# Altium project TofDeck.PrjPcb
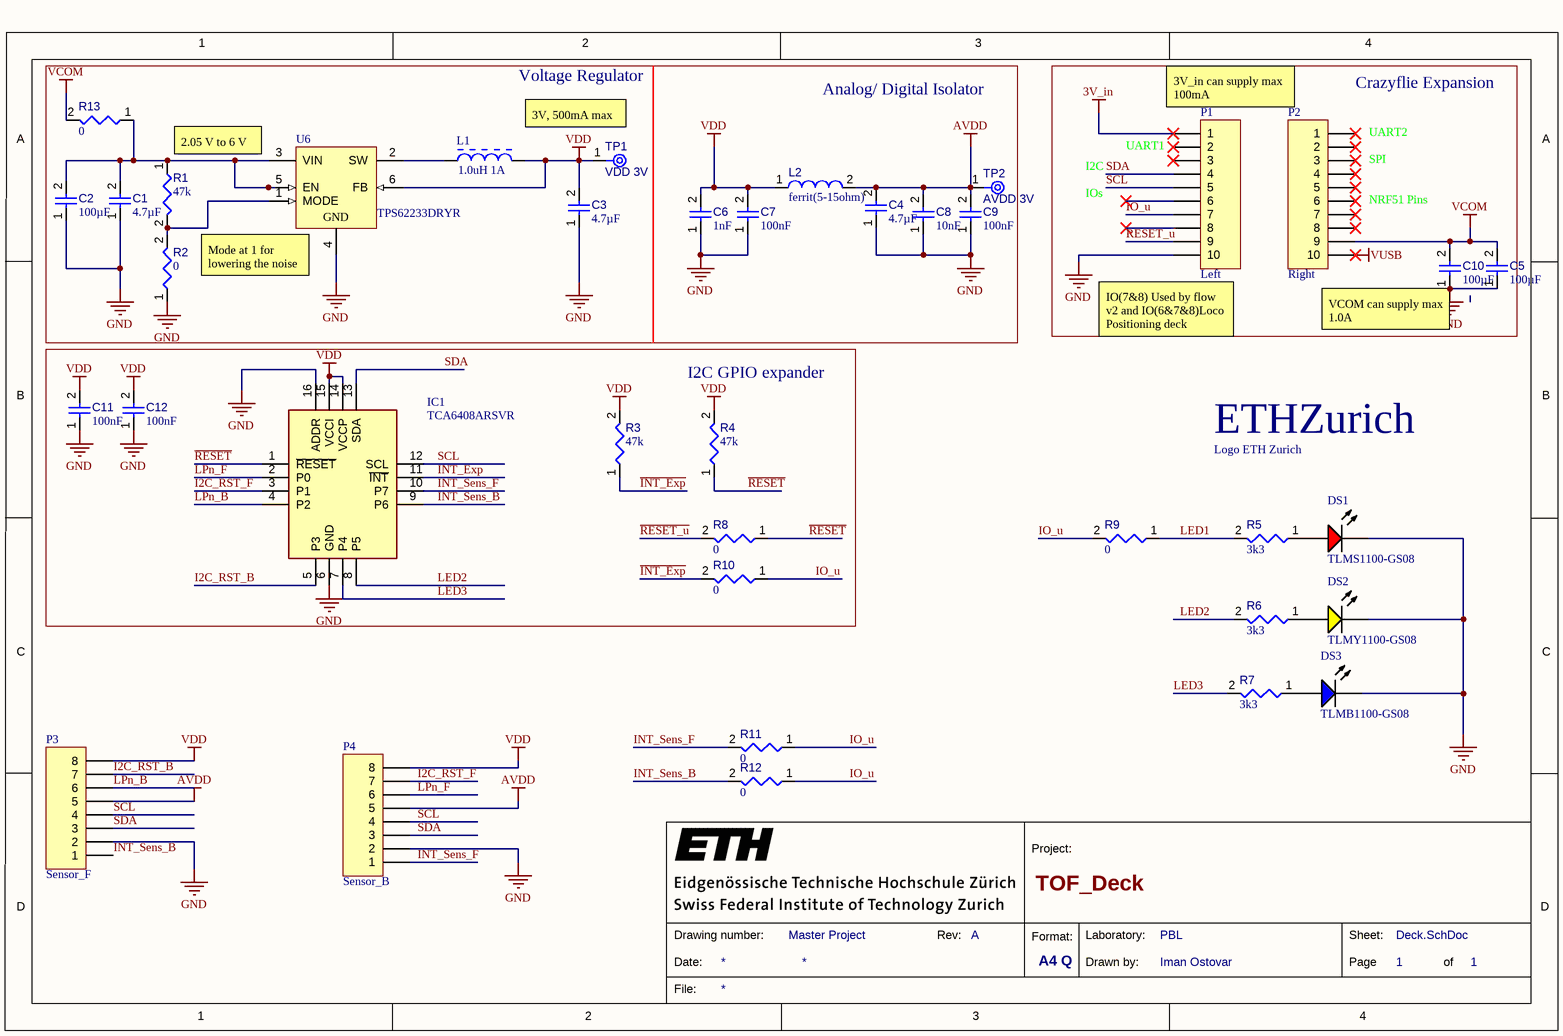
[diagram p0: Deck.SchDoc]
1 sheet, 39 parts. Net scope: global (net labels, ports and power ports of the same name join across sheets).
Board file: Deck.PcbDoc

## Sheet Deck.SchDoc: TOF_Deck
size A4; Author: Iman Ostovar; CompanyName: ETH Zürich; DrawnBy: Iman Ostovar; Engineer: Iman Ostovar; Organization: PBL; DocumentNumber: Master Project; Revision: A; SheetNumber: 1; SheetTotal: 1

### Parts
A1  Logo ETH Zurich  [eth-zurich_3mm]  (no BOM)
C1  value 4.7µF  [CAPC1005X55X25ML5T10]  (hidden comment: Capacitor 1 uF +/- 10% 6.3 V 1005)
C2  value 100µF  [CAPC0805(2012)145_L]  (hidden comment: Capacitor 100µF +/-20% 6.3V 0805)
C3  value 4.7µF  [CAPC1005X55X25ML5T10]  (hidden comment: Capacitor 1 uF +/- 10% 6.3 V 1005)
C4  value 4.7µF  [CAPC1005X55X25ML5T10]  (hidden comment: Capacitor 1 uF +/- 10% 6.3 V 1005)
C5  value 100µF  [CAPC0805(2012)145_L]  (hidden comment: Capacitor 100µF +/-20% 6.3V 0805)
C6  value 1nF  [CAPC0402(1005)60_L]  (hidden comment: Capacitor 100nF +/-20% 25V 0402)
C7  value 100nF  [CAPC0402(1005)60_L]  (hidden comment: Capacitor 100nF +/-20% 25V 0402)
C8  value 10nF  [CAPC0402(1005)60_L]  (hidden comment: Capacitor 100nF +/-20% 25V 0402)
C9  value 100nF  [CAPC0402(1005)60_L]  (hidden comment: Capacitor 100nF +/-20% 25V 0402)
C10  value 100µF  [CAPC0805(2012)145_L]  (hidden comment: Capacitor 100µF +/-20% 6.3V 0805)
C11  value 100nF  [CAPC0402(1005)60_L]  (hidden comment: Capacitor 100nF +/-20% 25V 0402)
C12  value 100nF  [CAPC0402(1005)60_L]  (hidden comment: Capacitor 100nF +/-20% 25V 0402)
DS1  TLMS1100-GS08  [VISH-TLMX1100_V]
DS2  TLMY1100-GS08  [VISH-TLMX1100-2_V]
DS3  TLMB1100-GS08  [VISH-TLMX1100-2_V]
IC1  TCA6408ARSVR  [QFN40P180X260X55-16N]
L1  1.0uH 1A  [INDC2013X105X50ML20T20]
L2  value ferrit(5-15ohm)  [MURA-LQP15MN3N6B02D-2_M]  (hidden comment: LQP15MN3N6B02D)
P1  Left  [PCBComponent_1]
P2  Right  [PCBComponent_1]
P3  Sensor_F  [MHDR1X8]
P4  Sensor_B  [MHDR1X8]
R1  value 47k  [RESC0402(1005)_L]  (hidden comment: Resistor 47K5 +/-1 % 0402 63 mW)
R2  value 0  [RESC0402(1005)_L]  (hidden comment: Jumper 0402)
R3  value 47k  [RESC0402(1005)_L]  (hidden comment: Resistor 47K5 +/-1 % 0402 63 mW)
R4  value 47k  [RESC0402(1005)_L]  (hidden comment: Resistor 47K5 +/-1 % 0402 63 mW)
R5  value 3k3  [RESC0402(1005)_L]  (hidden comment: Resistor 47K5 +/-1 % 0402 63 mW)
R6  value 3k3  [RESC0402(1005)_L]  (hidden comment: Resistor 47K5 +/-1 % 0402 63 mW)
R7  value 3k3  [RESC0402(1005)_L]  (hidden comment: Resistor 47K5 +/-1 % 0402 63 mW)
R8  value 0  [RESC0402(1005)_L]  (hidden comment: Jumper 0402)
R9  value 0  [RESC0402(1005)_L]  (hidden comment: Jumper 0402)
R10  value 0  [RESC0402(1005)_L]  (hidden comment: Jumper 0402)
R11  value 0  [RESC0402(1005)_L]  (hidden comment: Jumper 0402)
R12  value 0  [RESC0402(1005)_L]  (hidden comment: Jumper 0402)
R13  value 0  [RESC0402(1005)_L]  (hidden comment: Jumper 0402)
TP1  VDD 3V  [TP06R]  (no BOM)
TP2  AVDD 3V  [TP06R]  (no BOM)
U6  TPS62233DRYR  [DRY0006A]

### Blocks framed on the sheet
Crazyflie Expansion: C5 C10 P1 P2
I2C GPIO expander: C11 C12 IC1 R3 R4 R8 R10

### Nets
3V_in: P1.1
AVDD: C4.2 C8.2 C9.2 L2.2 P3.5 P4.5 TP2.1(TP)
GND: C1.1 C2.1 C3.1 C4.1 C5.1 C6.1 C7.1 C8.1 C9.1 C10.1 C11.1 C12.1 DS1.2(K) DS2.2(K) DS3.2(K) IC1.6(GND) IC1.16(ADDR) P1.10 P3.2 P4.2 R2.1 U6.4(GND)
VCOM: C5.2 C10.2 P2.9 R13.2
VDD: C3.2 C6.2 C7.2 C11.2 C12.2 IC1.14(VCCP) IC1.15(VCCI) L1.2 L2.1 P3.8 P4.8 R3.2 R4.2 TP1.1(TP) U6.6(FB)
VUSB: P2.10
~{INT_Exp}: IC1.11(~{INT}) R3.1 R10.2
~{RESET}: IC1.1(~{RESET}) R4.1 R8.1
~{RESET_u}: P1.9 R8.2
I2C_RST_B: IC1.5(P3) P3.7
I2C_RST_F: IC1.3(P1) P4.7
INT_Sens_B: IC1.9(P6) P3.1 R12.2
INT_Sens_F: IC1.10(P7) P4.1 R11.2
IO_u: P1.7 R9.2 R10.1 R11.1 R12.1
LED1: R5.2 R9.1
LED2: IC1.8(P5) R6.2
LED3: IC1.7(P4) R7.2
LPn_B: IC1.4(P2) P3.6
LPn_F: IC1.2(P0) P4.6
SCL: IC1.12(SCL) P1.5 P3.4 P4.4
SDA: IC1.13(SDA) P1.4 P3.3 P4.3
NetC1_2: C1.2 C2.2 R1.1 R13.1 U6.3(VIN) U6.5(EN)
NetDS1_1: DS1.1(A) R5.1
NetDS2_1: DS2.1(A) R6.1
NetDS3_1: DS3.1(A) R7.1
NetL1_1: L1.1 U6.2(SW)
NetR1_2: R1.2 R2.2 U6.1(MODE)

Not connected (* = marked no-connect by the designer): P1 2* 3* 6* 8*; P2 1* 2* 3* 4* 5* 6* 7* 8*

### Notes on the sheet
- Voltage Regulator
- Analog/ Digital Isolator
- 3V_in can supply max 100mA
- 2.05 V to 6 V
- 3V, 500mA max
- I2C
- (near P1) UART1
- (near P2) SPI
- (near P2) UART2
- IOs
- NRF51 Pins
- (near U6) Mode at 1 for lowering the noise
- (near P1) IO(7&8) Used by flow v2 and IO(6&7&8)Loco Positioning deck
- (near C10) VCOM can supply max 1.0A
- (near R3) Both SCL & SDA are already connected to the VCC with 2.2K pull up Res.

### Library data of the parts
A1 = CMP-00038-1
C1 C3 C4 = CMP-001-00009-6: Chip Capacitor, 1 uF, +/- 10%, 6.3 V, 1005 (0402 Metric); Voltage Rating: 6.3V; Capacitor Type: Ceramic
C2 C5 C10 = CMP-001-00054-4: Chip Capacitor, 100µF +/-20%, 6.3V, 0805, Thickness 1.45 mm; Tolerance: 10%
C6-C9 C11 C12 = CMP-001-00065-4: Chip Capacitor, 100nF +/-20%, 25V, 0402, Thickness 0.6 mm; Tolerance: 10%
DS1 = CMP-007-00030-2: Red Led, 20mA, 2.1 V, -40 to 100 degC, 2-Pin SMD (0603), RoHS, Tape and Reel; Manufacturer: Vishay Semiconductor; Viewing Angle: 160degrees; Forward Voltage: 2.1V; Lens Style: Clear; Power: 90mW; Luminous Intensity: 63mcd
DS2 = CMP-007-00031-2: Yellow LED, 20 mA, 2.1 V, -40 to 100 degC, 2-Pin SMD (0603), RoHS, Tape and Reel; Manufacturer: Vishay Semiconductor; Power: 90mW; Lens Style: Diffused; Nominal Vf: 2.1V; Forward Current: 20mA; Luminous Intensity: 80mcd; Viewing Angle: 160degrees
DS3 = CMP-007-00028-2: Blue LED, 10 mA, 3.9 V, -40 to 100 degC, 2-Pin SMD (0603), RoHS, Tape and Reel; Manufacturer: Vishay Semiconductor; Forward Voltage: 3.9V; Viewing Angle: 160degrees; Power: 68mW; Forward Current: 10mA; Lens Style: Diffused; Luminous Intensity: 5mcd
IC1 = TCA6408ARSVR: Integrated Circuit; Manufacturer_Name: Texas Instruments
L1 = CMP-006-00000-3: 1.0uH 1150mA; Manufacturer: Murata; Core Material: Ferrite; Current Rating: 1.5A; Impedance: 330Ohm; Resistance: 90mohm; Tolerance: 25%
L2 = CMP-006-00010-6: Inductor, 500 MHz, 500 mA, 5 Ohm, -40 to 85 degC, 01005 (0402 Metric),; Manufacturer: Murata; Core Material: Ferrite; Self Resonant Frequency: 6GHz; Current Rating: 170mA; Shielding: Unshielded; Q Factor: 13
P1 P2 = MHDR1X10: Header, 10-Pin
P3 = MHDR1X8: Header, 8-Pin; system: Connector
P4 = MHDR1X8: Header, 8-Pin; System: Connector
R1 R3-R7 = CMP-009-00137-3: Chip Resistor, 47,5 kOhms, +/-1 %, 63 mW, -55 to 155 degC, 0402; Power: 63mW; Tolerance: 1%
R2 R8-R12 = CMP-009-00148-3
R13 = CMP-009-00148-3: Current sensing jumper OR Fuse
TP1 TP2 = CMP-00028-00002-2: 0.6mm round
U6 = CMP-0323-00281-3: Buck Step Down Regulator with 2.05 to 6 V Input and 3 V Output, -40 to 85 degC, 6-Pin SON (DRY), Green (RoHS & no Sb/Br); Manufacturer: Texas Instruments; Vin(Max)(V): 6; Synchronous Rectification: False; Regulated Outputs(#): 1; SubFamily: Step-Down Regulator; Rating: Catalog; Preset Vout(V): 3; Vin(Min)(V): 2.05; Iq(Typ)(mA): 0.022; Duty Cycle(Max)(%): 100; Switch Current Limit(Typ)(A): 0.84; Iout(Max)(A): 0.5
